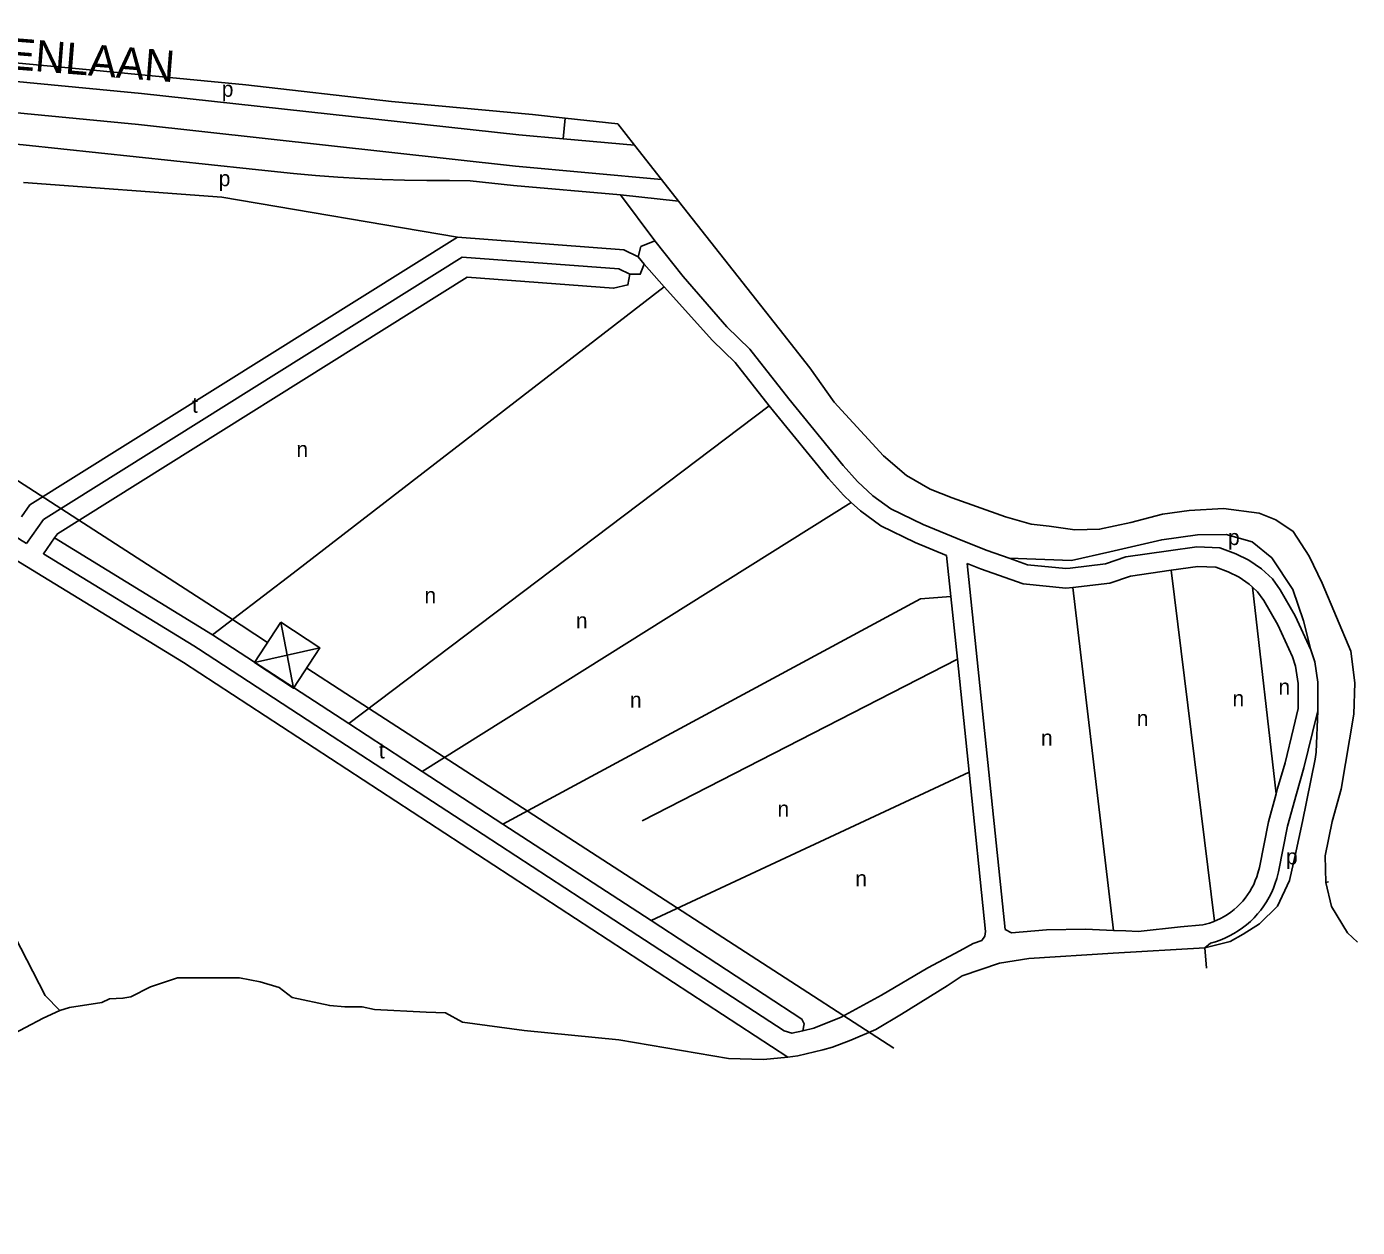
# Model space of a CAD drawing. Extents: x 161773 to 163836, y 384796 to 386521.
# Drawn here: x 163495.8 to 163835.7, y 386214 to 386520.8 of the extents above; entities that cross this region are included whole.
import ezdxf

# ---------------------------------------------------------------- set-up
doc = ezdxf.new("R2010")
doc.units = 0
for name, color, linetype in [('BLT_Basislijn', 7, 'Continuous'), ('BLT_Centroide', 7, 'Continuous'), ('BLT_Gemeentegrens', 7, 'Continuous'), ('BLT_Hoogspanningsmast_en_leidingen', 7, 'Continuous'), ('BLT_Straatnaam_hoofdweg', 7, 'Continuous'), ('BLT_Vlakafsluiter', 7, 'Continuous')]:
    doc.layers.add(name, color=color, linetype=linetype)

msp = doc.modelspace()

# ---------------------------------------------------------------- linework, layer by layer
at = {"layer": 'BLT_Basislijn'}
for p, q in [((163633.3, 386497.46), (163632.77, 386492.16)), ((163632.77, 386492.16), (163621.51, 386493.15)), ((163651.01, 386490.54), (163632.77, 386492.16)), ((163657.95, 386481.73), (163620.64, 386485.2)), ((163647.45, 386477.81), (163620.09, 386480.23)), ((163647.45, 386477.81), (163662.28, 386476.23)), ((163647.45, 386477.81), (163656.19, 386466.07)), ((163656.19, 386466.07), (163663.46, 386456.96)), ((163653.53, 386460.08), (163658.6, 386454.31)), ((163658.6, 386454.31), (163563.86, 386381.18)), ((163578.07, 386342.75), (163685.45, 386423.89)), ((163596.78, 386330.53), (163706.41, 386399.24)), ((163799.16, 386292.23), (163788.1, 386381.96)), ((163548.71, 386369.59), (163563.86, 386381.18)), ((163762.99, 386377.53), (163773.39, 386289.89)), ((163808.89, 386377.61), (163814.91, 386324.75)), ((163543.26, 386365.45), (163578.07, 386342.75)), ((163538.47, 386362.61), (163539.7, 386361.81)), ((163539.7, 386361.81), (163573.83, 386339.54)), ((163535.8, 386358.38), (163690.16, 386257.51)), ((163653, 386317.88), (163733.49, 386359.21)), ((163578.07, 386342.75), (163596.78, 386330.53)), ((163573.83, 386339.54), (163592.12, 386327.61)), ((163592.12, 386327.61), (163612.41, 386314.37)), ((163596.78, 386330.53), (163617.42, 386317.07)), ((163655.25, 386292.39), (163736.48, 386330.31)), ((163617.42, 386317.07), (163655.25, 386292.39)), ((163612.41, 386314.37), (163649.91, 386289.9))]:
    msp.add_line(p, q, dxfattribs=at)
for points in [[(163427.59, 386516.49), (163471.98, 386513.48), (163511.02, 386509.9), (163551.8, 386505.9), (163588.97, 386501.7), (163625.02, 386498.38), (163633.3, 386497.46)], [(163621.51, 386493.15), (163525.14, 386503.76), (163462.02, 386509.8), (163427.23, 386511.66)], [(163620.64, 386485.2), (163524.32, 386495.8), (163461.43, 386501.82), (163426.91, 386503.66), (163400.36, 386504.23), (163349.66, 386503.42), (163297.37, 386502.98), (163274.52, 386502.52)], [(163633.3, 386497.46), (163646.74, 386495.96)], [(163552.61, 386484.49), (163494.87, 386490.6), (163455.26, 386494.1), (163450.21, 386494.49)], [(163552.61, 386484.49), (163558.26, 386483.84), (163563.92, 386483.27), (163569.58, 386482.78), (163575.26, 386482.36), (163580.93, 386482.03), (163586.62, 386481.78), (163592.3, 386481.6), (163597.99, 386481.51), (163603.68, 386481.5), (163603.8, 386481.5)], [(163605.79, 386467.01), (163545.62, 386477.2), (163495, 386480.96)], [(163609.07, 386481.44), (163603.8, 386481.5)], [(163620.09, 386480.23), (163609.07, 386481.44)], [(163494.47, 386395.59), (163496.61, 386398.63), (163605.79, 386467.01)], [(163605.79, 386467.01), (163648.33, 386463.8)], [(163648.33, 386463.8), (163651.99, 386462.03)], [(163651.99, 386462.03), (163652.66, 386464.6), (163656.19, 386466.07)], [(163495.77, 386388.75), (163500.12, 386394.92), (163607.05, 386461.9), (163647.01, 386458.89), (163649.8, 386457.53)], [(163653.53, 386460.08), (163652.52, 386457.53), (163649.8, 386457.53)], [(163651.99, 386462.03), (163653.53, 386460.08)], [(163502.92, 386390.22), (163503.63, 386391.22), (163608.31, 386456.79), (163645.68, 386453.98), (163649.34, 386454.82), (163649.8, 386457.53)], [(163663.46, 386456.96), (163674.58, 386444.11), (163680.45, 386438.36), (163690.41, 386425.67), (163704.35, 386408.64), (163707.96, 386404.62)], [(163658.6, 386454.31), (163670.98, 386440.64), (163676.72, 386435.01), (163685.45, 386423.89)], [(163685.45, 386423.89), (163686.51, 386422.54), (163700.56, 386405.39), (163704.39, 386401.12), (163706.41, 386399.24)], [(163463.98, 386410.78), (163493.92, 386389.88), (163495.77, 386388.75)], [(163461.12, 386406.68), (163491.18, 386385.69), (163535.8, 386358.38)], [(163746.7, 386384.99), (163741.14, 386386.95), (163734.87, 386389.4), (163724.74, 386393.59), (163716.53, 386397.61), (163711.92, 386400.94), (163707.96, 386404.62)], [(163730.74, 386385.7), (163722.68, 386389.03), (163713.95, 386393.3), (163708.74, 386397.07), (163706.41, 386399.24)], [(163502.92, 386390.22), (163500.04, 386386.13), (163538.47, 386362.61)], [(163502.92, 386390.22), (163543.26, 386365.45)], [(163823.79, 386361.59), (163821.9, 386369.01), (163819.22, 386376.98), (163813.81, 386385.05), (163808.82, 386389.14), (163802.16, 386391.05), (163794.84, 386390.97), (163785.68, 386389.72), (163772.45, 386386.64), (163762.62, 386384.39), (163746.7, 386384.99)], [(163731.83, 386375.22), (163730.74, 386385.7)], [(163823.79, 386361.59), (163819.81, 386370.24), (163815.96, 386376.88), (163813.96, 386379.73), (163811.17, 386382.31), (163807.95, 386384.51), (163804.65, 386386.13), (163800.55, 386387.65), (163794.7, 386387.89), (163787.39, 386386.91), (163776.54, 386385.3), (163771.35, 386383.55), (163762.33, 386382.48)], [(163762.99, 386377.53), (163761.21, 386377.32), (163750.3, 386378.41), (163739.39, 386382.26), (163735.98, 386383.6)], [(163747.36, 386289.23), (163745.68, 386290.15), (163735.98, 386383.6)], [(163762.33, 386382.48), (163761.17, 386382.35), (163751.4, 386383.33), (163746.7, 386384.99)], [(163788.1, 386381.96), (163777.71, 386380.42), (163772.46, 386378.64), (163762.99, 386377.53)], [(163808.89, 386377.61), (163808.05, 386378.39), (163805.43, 386380.18), (163802.68, 386381.53), (163799.55, 386382.69), (163794.93, 386382.88), (163788.1, 386381.96)], [(163617.42, 386317.07), (163724.06, 386374.58), (163731.83, 386375.22)], [(163733.49, 386359.21), (163731.83, 386375.22)], [(163814.91, 386324.75), (163815.3, 386326.15), (163817.2, 386332.7), (163819.32, 386341.6), (163820.56, 386346.59), (163820.56, 386352.95), (163819.88, 386357.37), (163819.12, 386359.78), (163815.37, 386367.94), (163811.75, 386374.18), (163810.17, 386376.43), (163808.89, 386377.61)], [(163543.26, 386365.45), (163548.71, 386369.59)], [(163825.56, 386345.98), (163825.56, 386353.33), (163824.76, 386358.51), (163823.79, 386361.59)], [(163736.48, 386330.31), (163733.49, 386359.21)], [(163825.56, 386345.98), (163825.11, 386335.46), (163824.9, 386333.68), (163821.64, 386317.72), (163819.79, 386308.99), (163818.29, 386302.6), (163815.22, 386296.04), (163810.66, 386291.56), (163806.51, 386288.96), (163803.16, 386287.04), (163796.71, 386285.44)], [(163815.51, 386304.85), (163817.82, 386316.51), (163820.11, 386324.79), (163822.03, 386331.42), (163824.17, 386340.42), (163825.56, 386345.98)], [(163739.75, 386287.28), (163740.48, 386288.4), (163740.71, 386289.58), (163736.48, 386330.31)], [(163810.63, 386305.96), (163812.95, 386317.66), (163814.91, 386324.75)], [(163478.5, 386315.88), (163500.54, 386273.22), (163504.24, 386269.42)], [(163796.71, 386285.44), (163798.14, 386286.63), (163799.39, 386286.99), (163800.62, 386287.43), (163801.83, 386287.92), (163803, 386288.48), (163804.15, 386289.11), (163805.25, 386289.8), (163806.32, 386290.54), (163807.35, 386291.35), (163808.33, 386292.2), (163809.26, 386293.12), (163810.14, 386294.08), (163810.97, 386295.08), (163811.74, 386296.13), (163812.45, 386297.22), (163813.11, 386298.35), (163813.7, 386299.51), (163814.22, 386300.7), (163814.68, 386301.92), (163815.07, 386303.16), (163815.51, 386304.85)], [(163799.16, 386292.23), (163799.79, 386292.49), (163800.72, 386292.94), (163801.63, 386293.43), (163802.5, 386293.97), (163803.35, 386294.56), (163804.16, 386295.2), (163804.93, 386295.88), (163805.67, 386296.6), (163806.37, 386297.36), (163807.02, 386298.15), (163807.63, 386298.98), (163808.19, 386299.84), (163808.71, 386300.74), (163809.18, 386301.65), (163809.59, 386302.6), (163809.96, 386303.56), (163810.27, 386304.54), (163810.63, 386305.96)], [(163649.91, 386289.9), (163689.29, 386264.21), (163691.24, 386263.62), (163694.02, 386264.25)], [(163655.25, 386292.39), (163693.8, 386267.23), (163694.35, 386266.03), (163694.02, 386264.25)], [(163747.36, 386289.23), (163756.25, 386290.04), (163766.19, 386290.23), (163773.39, 386289.89)], [(163773.39, 386289.89), (163776.55, 386289.75), (163779.65, 386289.6), (163790.45, 386290.79), (163796.2, 386291.31)], [(163796.2, 386291.31), (163796.88, 386291.47), (163797.87, 386291.76), (163798.84, 386292.1), (163799.16, 386292.23)], [(163694.02, 386264.25), (163696.81, 386264.88), (163696.86, 386264.89), (163703.81, 386267.72), (163714.12, 386273.38), (163725.92, 386280.33), (163734.14, 386284.66), (163737.52, 386286.54)], [(163737.52, 386286.54), (163739.75, 386287.28)], [(163690.16, 386257.51), (163692.73, 386257.82), (163699.14, 386259.36), (163701.64, 386260.08), (163706.29, 386261.83), (163712.63, 386264.56), (163719.24, 386268.46), (163730.87, 386275.74), (163734.72, 386278.24), (163744.23, 386281.52), (163751.71, 386282.71), (163773.26, 386284.1), (163796.71, 386285.44)], [(163690.16, 386257.51), (163683.96, 386256.9), (163675.05, 386257.19), (163646.99, 386261.95), (163622.84, 386264.32), (163607.12, 386266.44), (163602.73, 386268.79), (163597.82, 386268.97), (163584.64, 386269.7), (163581.44, 386270.33), (163577.08, 386270.35), (163573.18, 386270.67), (163563.61, 386272.75), (163560.26, 386275.32), (163555.42, 386276.75), (163550.12, 386277.78), (163534.33, 386277.74), (163527.43, 386275.51), (163522.37, 386272.89), (163520.37, 386272.55), (163516.97, 386272.37), (163514.97, 386271.45), (163506.76, 386270.16), (163504.24, 386269.42)], [(163504.24, 386269.42), (163500, 386267.48), (163490.93, 386262.66), (163488.24, 386260.67), (163484.19, 386258.44), (163483.07, 386256.62), (163480.07, 386253.04), (163478.74, 386250.15), (163477.53, 386248.99), (163473.3, 386247.13), (163471.18, 386240.92), (163468.46, 386237.69), (163466.64, 386234.55), (163463.58, 386231.49), (163461.82, 386228.72), (163459.34, 386226.7), (163458.3, 386224.8), (163455.04, 386223.61), (163451.15, 386218.78), (163449.19, 386214.68), (163449.02, 386214)]]:
    msp.add_lwpolyline(points, dxfattribs=at)
at = {"layer": 'BLT_Gemeentegrens'}
for p, q in [((163651.01, 386490.54), (163646.74, 386495.96)), ((163657.95, 386481.73), (163651.01, 386490.54)), ((163662.28, 386476.23), (163657.95, 386481.73))]:
    msp.add_line(p, q, dxfattribs=at)
for points in [[(163827.61, 386302.11), (163827.43, 386308.96), (163829.22, 386317.71), (163831.56, 386325.95), (163834.74, 386345.15), (163834.98, 386353.15), (163833.95, 386361.26), (163826.68, 386378.62), (163823.38, 386385.55), (163819.27, 386391.82), (163814.83, 386394.76), (163810.57, 386396.5), (163801.47, 386397.72), (163792.67, 386397.17), (163785.9, 386396.23), (163777.76, 386394.09), (163769.8, 386392.37), (163763.53, 386392.25), (163756.93, 386393.19), (163752.33, 386393.66), (163745.76, 386395.56), (163732.17, 386400.38), (163726.56, 386402.67), (163720.52, 386406.16), (163714.67, 386411.11), (163702.07, 386424.88), (163695.83, 386433.66), (163687.96, 386443.63), (163662.28, 386476.23)], [(163835.67, 386286.87), (163833.1, 386289.3), (163829.08, 386295.97), (163827.61, 386302.11)]]:
    msp.add_lwpolyline(points, dxfattribs=at)
at = {"layer": 'BLT_Hoogspanningsmast_en_leidingen'}
for p, q in [((163350, 386497.4), (163547.35, 386370)), ((163557.33, 386363.46), (163547.35, 386370)), ((163560.71, 386368.61), (163563.95, 386351.77)), ((163553.96, 386358.31), (163570.69, 386362.07)), ((163577.31, 386350.38), (163567.32, 386356.92)), ((163577.31, 386350.38), (163717.25, 386259.77))]:
    msp.add_line(p, q, dxfattribs=at)
msp.add_lwpolyline([(163560.71, 386368.61), (163553.96, 386358.31), (163563.95, 386351.77), (163570.69, 386362.07)], close=True, dxfattribs=at)
at = {"layer": 'BLT_Vlakafsluiter'}
for p, q in [((163827.61, 386302.11), (163828.28, 386302.32)), ((163796.71, 386285.44), (163797.13, 386280.21))]:
    msp.add_line(p, q, dxfattribs=at)

# ---------------------------------------------------------------- texts
at = {"layer": 'BLT_Centroide'}
for s, p in [('p', (163545.62, 386502.89)), ('p', (163544.84, 386480.04)), ('t', (163538.03, 386422.16)), ('n', (163564.68, 386410.82)), ('p', (163802.63, 386388.35)), ('n', (163597.38, 386373.5)), ('n', (163636.06, 386367.05)), ('n', (163815.5, 386350.13)), ('n', (163649.87, 386346.78)), ('n', (163803.77, 386347.17)), ('n', (163779.32, 386342.09)), ('t', (163585.74, 386333.84)), ('n', (163754.86, 386337.11)), ('n', (163687.56, 386318.96)), ('p', (163817.45, 386306.75)), ('n', (163707.43, 386301.17))]:
    msp.add_text(s, height=4, dxfattribs=at).set_placement(p)
at = {"layer": 'BLT_Straatnaam_hoofdweg'}
msp.add_text('STERRENLAAN', height=8, rotation=355.4284, dxfattribs=at).set_placement((163454.46, 386512.91))

doc.saveas('drawing.dxf')
